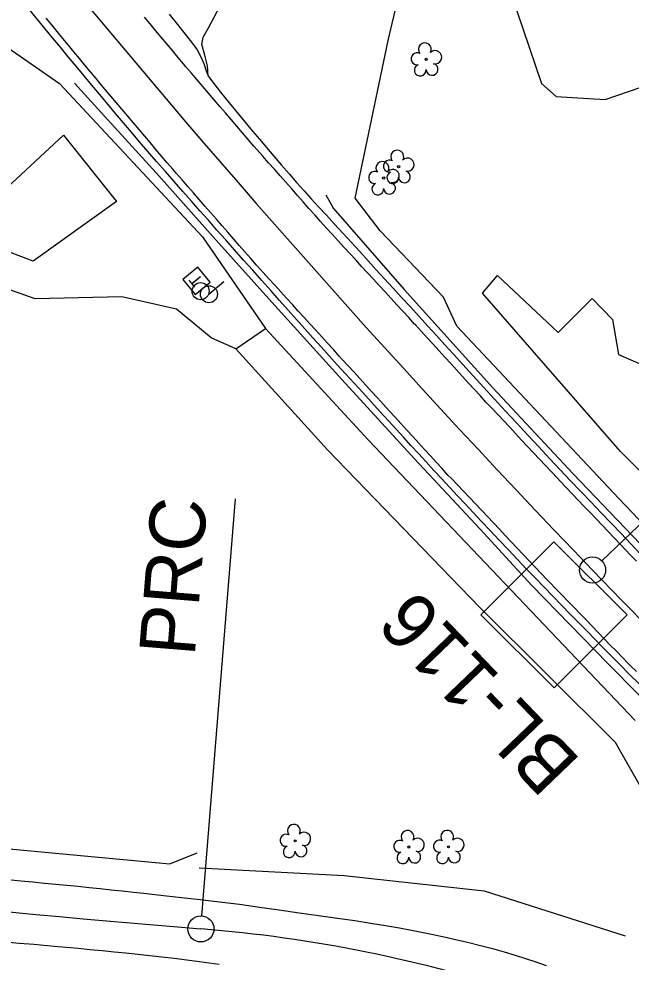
# Model space of a CAD drawing. Extents: x 474972 to 479313, y 498315 to 502691.
# Drawn here: x 476395.3 to 476570.9, y 500699.1 to 500969.8 of the extents above; entities that cross this region are included whole.
import ezdxf

# ---------------------------------------------------------------- set-up
doc = ezdxf.new("R2010")
doc.units = 0
for name, color, linetype in [('CTL Secondary Horizontal and Vertical CELL', 7, 'Continuous'), ('CTL Secondary Horizontal and Vertical Text', 7, 'Continuous'), ('Exist Guardrail', 7, 'Continuous'), ('Exist Horizontal Alignment', 7, 'Continuous'), ('Exist Other Culture Fence Line', 7, 'Continuous'), ('Exist Other Culture Gate', 7, 'Continuous'), ('Exist Roads EOP', 7, 'Continuous'), ('Exist Roads EOP Other', 7, 'Continuous'), ('Exist Roads EOT', 7, 'Continuous'), ('Exist Utilities Other Pole CELL', 7, 'Continuous'), ('Exist Utilities Power Pole CELL', 7, 'Continuous'), ('Exist Utilities Telephone Pedestal CELL', 7, 'Continuous'), ('Exist Vegetation Hedge Row', 7, 'Continuous'), ('Exist Vegetation Tree CELL', 7, 'Continuous'), ('Exist Vegetation Woods Line', 7, 'Continuous')]:
    doc.layers.add(name, color=color, linetype=linetype)

msp = doc.modelspace()

# ---------------------------------------------------------------- linework, layer by layer
at = {"layer": 'CTL Secondary Horizontal and Vertical CELL'}
msp.add_line((476548.71, 500798.68), (476548.71, 500798.68), dxfattribs=at)
msp.add_lwpolyline([(476527.85, 500798.76), (476548.81, 500819.72), (476569.81, 500798.72), (476548.85, 500777.75)], close=True, dxfattribs=at)
at = {"layer": 'Exist Guardrail'}
for points in [[(476581.97, 500766.87), (476564.28, 500784.78), (476542.44, 500807.12), (476527.59, 500823.29), (476508.83, 500843.5), (476487.98, 500866.28), (476467.88, 500888.44), (476450.94, 500907.28), (476434.71, 500925.56), (476419.91, 500941.81), (476411.27, 500951.34)], [(476483.37, 500919.24), (476485.61, 500915.36), (476505.87, 500892.09), (476531.29, 500863.92), (476554.3, 500839.18), (476575.59, 500816.95), (476608.03, 500783.92)]]:
    msp.add_lwpolyline(points, dxfattribs=at)
at = {"layer": 'Exist Horizontal Alignment'}
for p, q in [((476562.57, 500814.2), (476649.05, 500897.45)), ((476447.84, 500712.36), (476457.47, 500832))]:
    msp.add_line(p, q, dxfattribs=at)
for centre in [(476559.87, 500811.6), (476447.54, 500708.62)]:
    msp.add_circle(centre, 3.75, dxfattribs=at)
for centre, radius, start, end in [((478672.62, 502845.57), 2932.7, 213.99726, 223.91157), ((478884.49, 503049.53), 3226.8, 223.91157, 228.4381), ((476696.75, 503806.31), 3107.69, 261.3986, 265.40049), ((476415.01, 500304.21), 405.72, 71.839, 85.4005)]:
    msp.add_arc(centre, radius, start, end, dxfattribs=at)
at = {"layer": 'Exist Other Culture Fence Line'}
msp.add_line((476447, 500726.13), (476488.64, 500723.98), dxfattribs=at)
for points in [[(476239.65, 500757.8), (476250.32, 500756.64), (476272.68, 500754.03), (476284.64, 500752.07), (476323.41, 500742.23), (476345.63, 500738.53), (476367.99, 500735.09), (476393.64, 500731.52), (476438.64, 500727.27)], [(476488.64, 500723.98), (476528.82, 500719.55), (476569.26, 500706.67)]]:
    msp.add_lwpolyline(points, dxfattribs=at)
at = {"layer": 'Exist Other Culture Gate'}
msp.add_line((476438.64, 500727.27), (476446.45, 500730.46), dxfattribs=at)
at = {"layer": 'Exist Roads EOP'}
for points in [[(476573.2, 500778.95), (476570.4, 500781.75), (476567.76, 500784.41), (476565.27, 500786.93), (476562.92, 500789.3), (476560.63, 500791.64), (476558.29, 500794.03), (476555.9, 500796.47), (476553.46, 500798.96), (476550.99, 500801.5), (476548.5, 500804.06), (476546, 500806.64), (476543.48, 500809.25), (476540.94, 500811.89), (476538.36, 500814.59), (476535.74, 500817.35), (476533.08, 500820.16), (476530.47, 500822.94), (476527.97, 500825.6), (476525.6, 500828.14), (476523.34, 500830.55), (476521.13, 500832.92), (476518.9, 500835.32), (476516.65, 500837.75), (476514.38, 500840.2), (476512.13, 500842.64), (476509.93, 500845.03), (476507.79, 500847.37), (476505.71, 500849.66), (476503.58, 500851.99), (476501.34, 500854.45), (476498.97, 500857.04), (476496.48, 500859.75), (476493.95, 500862.51), (476491.47, 500865.22), (476489.05, 500867.87), (476486.67, 500870.47), (476484.33, 500873.05), (476481.99, 500875.64), (476479.67, 500878.22), (476477.35, 500880.82), (476475, 500883.45), (476472.58, 500886.16), (476470.1, 500888.94), (476467.55, 500891.81), (476464.97, 500894.71), (476462.39, 500897.62), (476459.8, 500900.53), (476457.22, 500903.44), (476454.66, 500906.33), (476452.14, 500909.17), (476449.68, 500911.96), (476447.25, 500914.7), (476444.83, 500917.44), (476442.37, 500920.23), (476439.87, 500923.07), (476437.34, 500925.96), (476434.82, 500928.85), (476432.36, 500931.69), (476429.97, 500934.47), (476427.65, 500937.2), (476425.36, 500939.9), (476423.08, 500942.61), (476420.81, 500945.31), (476418.55, 500948.02), (476416.28, 500950.73), (476414.02, 500953.45), (476411.75, 500956.16), (476409.49, 500958.89), (476407.24, 500961.59), (476405.02, 500964.28), (476402.83, 500966.94), (476400.68, 500969.58), (476398.54, 500972.2)], [(476438.46, 500971.08), (476440.84, 500968.13), (476442.69, 500965.81), (476444.85, 500963.09), (476446.47, 500960.86), (476447.46, 500959.09), (476448.39, 500956.94), (476449.16, 500954.58), (476449.47, 500953.84), (476449.85, 500953.09), (476450.26, 500952.44), (476453.18, 500948.75), (476455.63, 500945.69), (476458.77, 500941.8), (476462.35, 500937.49), (476464.3, 500935.19), (476466.32, 500932.81), (476468.43, 500930.35), (476470.62, 500927.81), (476472.83, 500925.28), (476475, 500922.82), (476477.12, 500920.43), (476479.2, 500918.13), (476481.31, 500915.81), (476483.52, 500913.39), (476485.83, 500910.87), (476488.26, 500908.25), (476490.71, 500905.59), (476493.12, 500902.96), (476495.5, 500900.35), (476497.84, 500897.78), (476500.19, 500895.19), (476502.6, 500892.54), (476505.08, 500889.84), (476507.61, 500887.09), (476510.16, 500884.33), (476512.66, 500881.6), (476515.12, 500878.91), (476517.54, 500876.25), (476520.03, 500873.5), (476522.71, 500870.56), (476525.57, 500867.41), (476528.63, 500864.06), (476531.78, 500860.62), (476534.94, 500857.17), (476538.11, 500853.74), (476541.29, 500850.31), (476544.44, 500846.92), (476547.55, 500843.61), (476550.6, 500840.38), (476553.59, 500837.22), (476556.55, 500834.12), (476559.47, 500831.05), (476562.36, 500828.02), (476565.23, 500825.01), (476568.06, 500822.04), (476570.87, 500819.1), (476573.65, 500816.19)], [(476392.26, 500722.76), (476395.86, 500722.43), (476399.33, 500722.11), (476402.66, 500721.79), (476405.9, 500721.48), (476409.13, 500721.16), (476412.32, 500720.84), (476415.5, 500720.52), (476418.65, 500720.19), (476421.8, 500719.86), (476424.95, 500719.53), (476428.09, 500719.2), (476431.15, 500718.87), (476436.81, 500718.25), (476441.97, 500717.67), (476447.31, 500717.06), (476452.91, 500716.41), (476458.59, 500715.68), (476464.31, 500714.86), (476470.02, 500714.06), (476475.71, 500713.28), (476481.29, 500712.51), (476486.71, 500711.75), (476491.68, 500711.01), (476496.2, 500710.29), (476500.45, 500709.6), (476504.49, 500708.92), (476508.41, 500708.21), (476514.19, 500707.03), (476518.18, 500706.15), (476520.19, 500705.69), (476524.05, 500704.78), (476527.73, 500703.87), (476531.22, 500702.96), (476534.54, 500702.05), (476537.68, 500701.12), (476540.66, 500700.16), (476543.63, 500699.17), (476546.59, 500698.15)], [(476452.79, 500698.42), (476447.08, 500699.21), (476443.5, 500699.67), (476439.9, 500700.11), (476436.36, 500700.53), (476432.87, 500700.92), (476429.42, 500701.29), (476426.03, 500701.63), (476422.68, 500701.96), (476419.24, 500702.3), (476415.72, 500702.65), (476412.3, 500702.97), (476408.98, 500703.27), (476405.42, 500703.6), (476399.61, 500704.13), (476395.53, 500704.48), (476391.35, 500704.85)]]:
    msp.add_lwpolyline(points, dxfattribs=at)
at = {"layer": 'Exist Roads EOP Other'}
msp.add_lwpolyline([(476449.62, 500953.29), (476449.48, 500956.3), (476448.64, 500959.36), (476447.85, 500962.41), (476448.23, 500964.55), (476449.74, 500967.22), (476452.24, 500971.87), (476454.23, 500974.05), (476456.25, 500976.34), (476459.66, 500978.54), (476465.16, 500981.77), (476466.88, 500984.18), (476474.12, 500987.47), (476481.77, 500990.97), (476488.54, 500993.36), (476499.49, 500995.91), (476512.39, 500998.83), (476529.89, 501003.07), (476550.35, 501008.9), (476564.57, 501012.02), (476582.26, 501017.67), (476590.57, 501020.86)], dxfattribs=at)
at = {"layer": 'Exist Roads EOT'}
for points in [[(476572.43, 500782.45), (476570.66, 500784.21), (476570.18, 500784.69), (476568.45, 500786.49), (476566.71, 500788.28), (476564.97, 500790.08), (476563.23, 500791.88), (476561.5, 500793.67), (476559.76, 500795.47), (476558.02, 500797.27), (476556.29, 500799.06), (476554.55, 500800.86), (476552.81, 500802.65), (476551.07, 500804.45), (476549.34, 500806.25), (476547.6, 500808.04), (476546.88, 500808.79), (476545.16, 500810.6), (476543.44, 500812.42), (476541.73, 500814.23), (476540.01, 500816.05), (476538.29, 500817.86), (476536.57, 500819.67), (476534.85, 500821.49), (476533.14, 500823.3), (476531.42, 500825.12), (476529.7, 500826.93), (476527.98, 500828.75), (476526.27, 500830.56), (476524.55, 500832.37), (476522.83, 500834.19), (476521.11, 500836), (476519.39, 500837.82), (476518.41, 500838.85), (476516.73, 500840.7), (476515.04, 500842.54), (476513.36, 500844.39), (476511.67, 500846.23), (476509.99, 500848.07), (476508.3, 500849.92), (476506.62, 500851.76), (476504.93, 500853.61), (476503.25, 500855.45), (476501.57, 500857.29), (476499.88, 500859.14), (476498.2, 500860.98), (476496.51, 500862.83), (476494.83, 500864.67), (476493.14, 500866.52), (476491.46, 500868.36), (476489.77, 500870.2), (476488.09, 500872.05), (476487.23, 500872.99), (476485.55, 500874.84), (476483.87, 500876.68), (476482.19, 500878.53), (476480.5, 500880.38), (476478.82, 500882.23), (476477.14, 500884.07), (476475.46, 500885.92), (476473.78, 500887.77), (476472.1, 500889.62), (476470.42, 500891.46), (476468.74, 500893.31), (476467.06, 500895.16), (476465.38, 500897.01), (476463.7, 500898.85), (476463.46, 500899.11), (476461.82, 500900.99), (476460.18, 500902.88), (476458.54, 500904.76), (476456.9, 500906.64), (476455.26, 500908.52), (476453.61, 500910.4), (476451.97, 500912.28), (476450.33, 500914.16), (476448.69, 500916.05), (476447.05, 500917.93), (476445.41, 500919.81), (476443.77, 500921.69), (476442.13, 500923.57), (476440.48, 500925.45), (476439.5, 500926.58), (476437.89, 500928.49), (476436.27, 500930.39), (476434.66, 500932.3), (476433.04, 500934.2), (476431.43, 500936.1), (476429.82, 500938.01), (476428.2, 500939.91), (476426.59, 500941.82), (476424.97, 500943.72), (476423.36, 500945.63), (476421.75, 500947.53), (476420.13, 500949.44), (476419.07, 500950.69), (476417.48, 500952.62), (476415.89, 500954.54), (476414.29, 500956.47), (476412.7, 500958.39), (476411.11, 500960.31), (476409.52, 500962.24), (476407.93, 500964.16), (476406.34, 500966.09), (476404.75, 500968.01), (476403.16, 500969.93)], [(476572.44, 500814.17), (476570.7, 500815.97), (476569.51, 500817.19), (476567.79, 500819), (476566.07, 500820.81), (476564.35, 500822.63), (476562.63, 500824.44), (476560.91, 500826.25), (476559.19, 500828.06), (476557.47, 500829.87), (476555.75, 500831.68), (476554.03, 500833.5), (476552.31, 500835.31), (476550.59, 500837.12), (476549.77, 500837.98), (476548.06, 500839.8), (476546.35, 500841.62), (476544.64, 500843.44), (476542.93, 500845.26), (476541.23, 500847.08), (476539.52, 500848.91), (476537.81, 500850.73), (476536.1, 500852.55), (476534.39, 500854.37), (476532.68, 500856.19), (476530.97, 500858.01), (476529.29, 500859.8), (476527.61, 500861.64), (476525.92, 500863.49), (476524.24, 500865.33), (476522.56, 500867.18), (476520.87, 500869.02), (476519.19, 500870.87), (476517.5, 500872.71), (476515.82, 500874.56), (476514.14, 500876.4), (476512.45, 500878.25), (476510.77, 500880.09), (476509.08, 500881.94), (476508.85, 500882.19), (476507.16, 500884.03), (476505.47, 500885.87), (476503.78, 500887.71), (476502.09, 500889.55), (476500.4, 500891.39), (476498.71, 500893.23), (476497.02, 500895.06), (476495.33, 500896.9), (476493.64, 500898.74), (476491.95, 500900.58), (476490.26, 500902.42), (476488.57, 500904.26), (476486.88, 500906.1), (476485.19, 500907.94), (476483.51, 500909.77), (476481.85, 500911.63), (476480.2, 500913.5), (476478.54, 500915.37), (476476.89, 500917.24), (476475.23, 500919.11), (476473.58, 500920.98), (476471.92, 500922.85), (476470.26, 500924.72), (476468.61, 500926.59), (476466.95, 500928.46), (476465.3, 500930.33), (476463.64, 500932.2), (476462.7, 500933.27), (476461.07, 500935.16), (476459.45, 500937.06), (476457.82, 500938.95), (476456.2, 500940.85), (476454.58, 500942.75), (476452.95, 500944.64), (476451.33, 500946.54), (476449.7, 500948.44), (476448.08, 500950.33), (476446.46, 500952.23), (476444.83, 500954.13), (476443.21, 500956.02), (476442.54, 500956.81), (476440.94, 500958.73), (476439.35, 500960.65), (476437.75, 500962.57), (476436.15, 500964.49), (476434.56, 500966.41), (476432.96, 500968.33), (476431.37, 500970.25)]]:
    msp.add_lwpolyline(points, dxfattribs=at)
at = {"layer": 'Exist Utilities Other Pole CELL'}
msp.add_circle((476447.45, 500891.62), 2.46, dxfattribs=at)
at = {"layer": 'Exist Utilities Power Pole CELL'}
for q in [(476454.12, 500894.39), (476449.84, 500890.74)]:
    msp.add_line((476449.84, 500890.74), q, dxfattribs=at)
msp.add_circle((476449.84, 500890.74), 2.45, dxfattribs=at)
at = {"layer": 'Exist Utilities Telephone Pedestal CELL'}
msp.add_line((476446.29, 500894.52), (476446.29, 500894.52), dxfattribs=at)
msp.add_lwpolyline([(476450.2, 500894.19), (476446.67, 500898.53), (476442.33, 500895), (476445.86, 500890.66), (476450.2, 500894.19)], dxfattribs=at)
at = {"layer": 'Exist Vegetation Hedge Row'}
for points in [[(476611.27, 500785.98), (476567.44, 500832.14), (476520.96, 500881.55), (476517.12, 500889.87), (476499, 500908.92), (476491.76, 500918.33), (476501.29, 500963.57), (476506.79, 500987.16), (476516.6, 500988.45), (476523.48, 500988.1), (476534.73, 500982.27), (476545.27, 500951.19), (476549.43, 500947.45), (476563.45, 500946.58), (476573.86, 500950.18), (476600.17, 500925.94), (476612.97, 500917.6), (476590.15, 500884.72), (476588.49, 500873.42), (476595.28, 500853.23)], [(476387.51, 500964.69), (476406.97, 500951.24), (476447.99, 500907.24), (476466.04, 500880.93)], [(476457.55, 500875.04), (476450.44, 500878.26), (476440.52, 500886.42), (476424.84, 500889.98), (476400, 500889.45), (476391.07, 500892.58), (476382.67, 500893.18), (476375.97, 500888.51), (476363.7, 500885.44), (476355.9, 500884.59), (476337.73, 500880.49)]]:
    msp.add_lwpolyline(points, dxfattribs=at)
at = {"layer": 'Exist Vegetation Tree CELL'}
for p, q in [((476512.15, 500958.16), (476512.15, 500958.16)), ((476504.25, 500927.31), (476504.25, 500927.31)), ((476499.98, 500924.06), (476499.98, 500924.06)), ((476474.57, 500733.9), (476474.57, 500733.9)), ((476507.18, 500732.15), (476507.18, 500732.15)), ((476518.56, 500732.17), (476518.56, 500732.17))]:
    msp.add_line(p, q, dxfattribs=at)
for centre in [(476512.15, 500958.16), (476504.25, 500927.31), (476499.98, 500924.06), (476474.57, 500733.9), (476507.18, 500732.15), (476518.56, 500732.17)]:
    msp.add_circle(centre, 0.326, dxfattribs=at)
for centre, radius, start, end in [((476511.77, 500961.03), 1.86, 330.1651, 219.7134), ((476509.54, 500958.31), 1.73, 62.6636, 279.3457), ((476514.7, 500958.75), 1.9, 257.1011, 134.1999), ((476510.45, 500955.04), 1.69, 111.5671, 6.231), ((476513.82, 500955.26), 1.7, 181.2822, 74.56), ((476503.87, 500930.18), 1.86, 330.1651, 219.7134), ((476501.65, 500927.46), 1.73, 62.6636, 279.3457), ((476506.8, 500927.9), 1.9, 257.1011, 134.1999), ((476499.59, 500926.93), 1.86, 330.1651, 219.7134), ((476502.53, 500924.65), 1.9, 257.1011, 134.1999), ((476497.37, 500924.21), 1.73, 62.6636, 279.3457), ((476502.55, 500924.19), 1.69, 111.5671, 6.231), ((476505.92, 500924.41), 1.7, 181.2822, 74.56), ((476498.27, 500920.94), 1.69, 111.5671, 6.231), ((476501.65, 500921.16), 1.7, 181.2822, 74.56), ((476474.19, 500736.77), 1.86, 330.1651, 219.7134), ((476471.97, 500734.05), 1.73, 62.6636, 279.3457), ((476477.12, 500734.48), 1.9, 257.1011, 134.1999), ((476506.79, 500735.03), 1.86, 330.1651, 219.7134), ((476509.72, 500732.74), 1.9, 257.1011, 134.1999), ((476518.17, 500735.05), 1.86, 330.1651, 219.7134), ((476521.11, 500732.76), 1.9, 257.1011, 134.1999), ((476472.87, 500730.77), 1.69, 111.5671, 6.231), ((476476.25, 500731), 1.7, 181.2822, 74.56), ((476504.57, 500732.31), 1.73, 62.6636, 279.3457), ((476515.95, 500732.33), 1.73, 62.6636, 279.3457), ((476505.47, 500729.03), 1.69, 111.5671, 6.231), ((476508.85, 500729.25), 1.7, 181.2822, 74.56), ((476516.85, 500729.05), 1.69, 111.5671, 6.231), ((476520.23, 500729.27), 1.7, 181.2822, 74.56)]:
    msp.add_arc(centre, radius, start, end, dxfattribs=at)
at = {"layer": 'Exist Vegetation Woods Line'}
for points in [[(476362.27, 500893.85), (476408.14, 500936.38), (476423.34, 500917.32), (476399.44, 500900.25), (476381.66, 500906.96), (476365.52, 500889.99), (476362.27, 500893.85)], [(476618.41, 500793.51), (476593.19, 500820.35), (476567.92, 500845.61), (476528.31, 500891.08), (476532.59, 500896.12), (476550.03, 500879.76), (476559.74, 500889.54), (476565.56, 500883.53), (476567.34, 500873.43), (476581.44, 500867.31), (476595.28, 500853.23), (476635.37, 500806.49)], [(476457.55, 500875.04), (476466.04, 500880.93)], [(476466.04, 500880.93), (476495.51, 500848.97), (476572.06, 500768.46)], [(476566.43, 500762.14), (476527.44, 500800.9), (476483.86, 500846.08), (476457.55, 500875.04)], [(476600.68, 500710.32), (476598.45, 500711.68), (476582.82, 500733.31), (476566.43, 500762.14)]]:
    msp.add_lwpolyline(points, dxfattribs=at)

# ---------------------------------------------------------------- texts
at = {"layer": 'CTL Secondary Horizontal and Vertical Text'}
msp.add_text('BL-116', height=16, rotation=133.8723, dxfattribs=at).set_placement((476556.91, 500756.83))
at = {"layer": 'Exist Horizontal Alignment'}
msp.add_text('PRC', height=16, rotation=85.4005, dxfattribs=at).set_placement((476445.74, 500786.63))
at = {"layer": 'Exist Utilities Telephone Pedestal CELL'}
msp.add_text('T', height=3.42, rotation=129.1033, dxfattribs=at).set_placement((476448.33, 500894.72))

doc.saveas('drawing.dxf')
